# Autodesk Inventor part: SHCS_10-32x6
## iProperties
Shininess: 0.0
Length Units: 11272
Angle Units: 11279
Time Units: 11290
Mass Units: 11283
Length Display Precision: 2
Angle Display Precision: 1
Created: 1999-05
Part Number: SHCS_10-32x6
Document SubType Name: Modeling
Designer: Administrator
Density: 1 g/cm^3
Density: 0.0
Volumn: 0.0
Area: 0.0
PropertySet Name: Model Information
Control State: 0
Master: False
Checked Out: False
Author: Administrator
